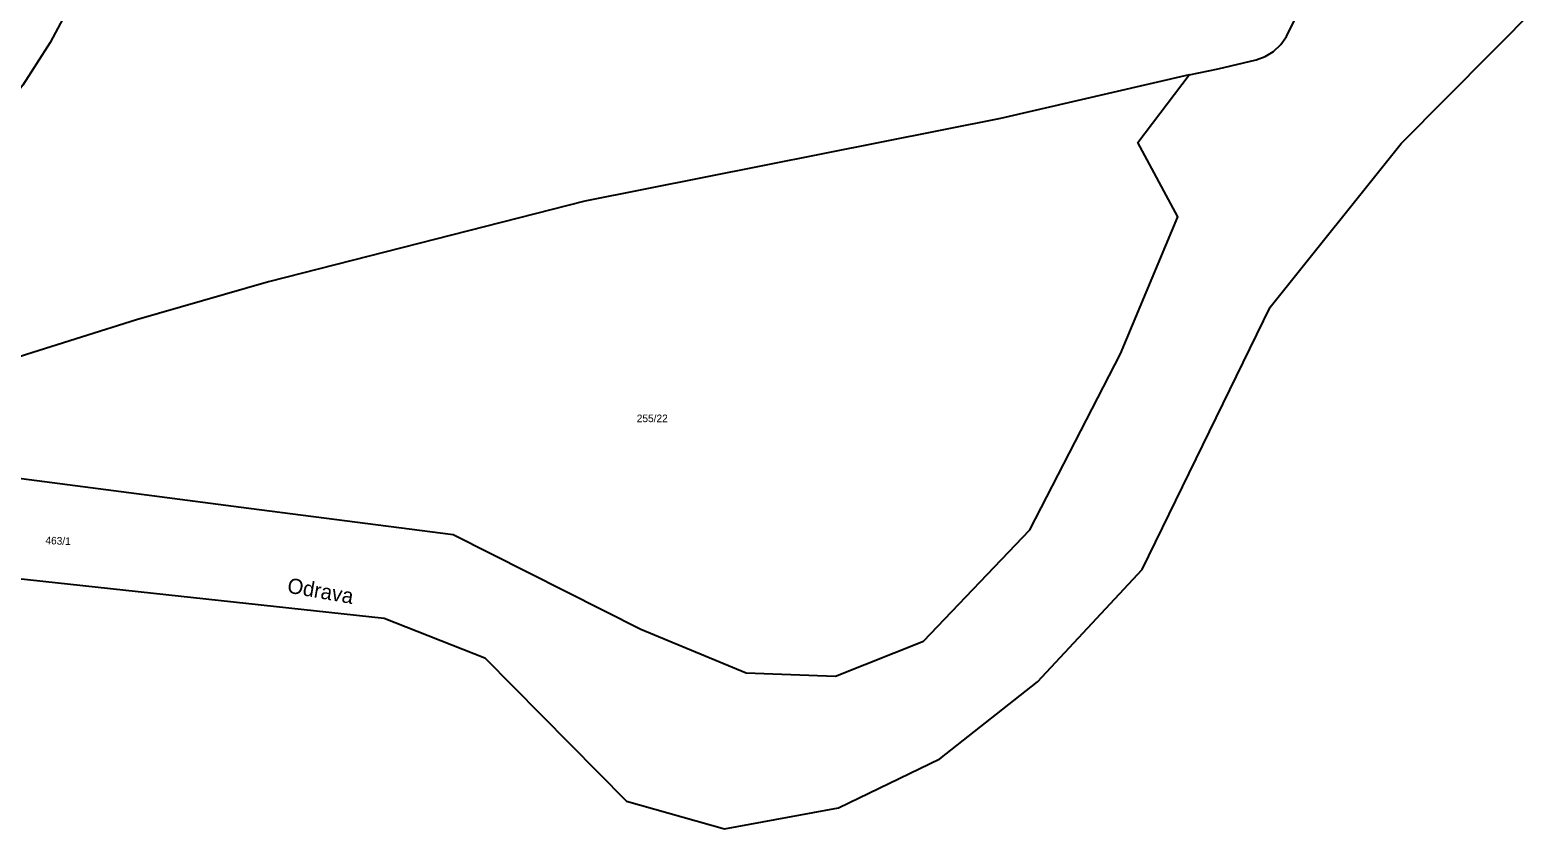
# Model space of a CAD drawing. Extents: x -882150 to -879379, y -1022570 to -1019819.
# Drawn here: x -880115.3 to -879777.5, y -1020976 to -1020796.9 of the extents above; entities that cross this region are included whole.
import ezdxf

# ---------------------------------------------------------------- set-up
doc = ezdxf.new("R2010")
doc.units = 0
for name, color, linetype in [('Hranice parcel', 7, 'Continuous'), ('Parcelní čísla', 7, 'Continuous'), ('Pop  PČ popisy', 7, 'Continuous')]:
    doc.layers.add(name, color=color, linetype=linetype)

msp = doc.modelspace()

# ---------------------------------------------------------------- linework, layer by layer
at = {"layer": 'Hranice parcel'}
msp.add_line((-880013.41, -1020937.59), (-879981.7, -1020969.74), dxfattribs=at)
for points in [[(-879855.67, -1020806.93), (-879849.12, -1020805.59), (-879840.65, -1020803.59), (-879838.63, -1020802.86), (-879836.73, -1020801.7), (-879835.11, -1020800.17), (-879833.86, -1020798.37), (-879828.56, -1020787.58), (-879810.46, -1020751.56), (-879811.09, -1020749.56), (-879813.66, -1020745.92), (-879816.39, -1020744.12), (-879819.42, -1020743.08), (-879822.57, -1020742.71), (-879825.01, -1020742.84)], [(-880104.98, -1020788.72), (-880110.84, -1020799.71), (-880116.96, -1020809.22), (-880122.17, -1020815.79)], [(-879981.7, -1020969.74), (-879959.72, -1020975.95), (-879934.19, -1020971.25), (-879911.49, -1020960.29), (-879889.63, -1020942.98), (-879866.16, -1020917.83), (-879837.52, -1020859.01), (-879808.19, -1020822.32), (-879777.54, -1020791.45)], [(-879855.67, -1020806.93), (-879897.91, -1020816.71), (-879991.04, -1020835.27), (-880061.88, -1020853.33), (-880091.47, -1020861.88), (-880116.15, -1020869.62), (-880138.18, -1020877.13), (-880170.25, -1020889.4), (-880175.6, -1020891.87), (-880180.75, -1020895.93), (-880182.85, -1020897), (-880185.19, -1020898.34), (-880186.1, -1020899.24), (-880186.44, -1020900.39), (-880186.27, -1020901.44), (-880183.95, -1020906.85), (-880183.54, -1020908.65), (-880183.84, -1020910.43), (-880184.81, -1020911.94), (-880186.2, -1020912.94), (-880194.71, -1020916.87), (-880183.87, -1020928.56), (-880181.15, -1020928.81), (-880176.17, -1020927.49)], [(-880176.17, -1020927.49), (-880173.52, -1020920.87), (-880157.73, -1020903.11), (-880135.62, -1020895), (-880066.31, -1020904.04), (-880020.56, -1020909.99), (-879978.51, -1020931.21), (-879954.91, -1020940.95), (-879934.91, -1020941.76), (-879915.17, -1020933.91), (-879891.35, -1020908.94), (-879871.04, -1020869.47), (-879858.22, -1020838.74), (-879867.14, -1020822.1), (-879855.67, -1020806.93)], [(-880124.94, -1020919.09), (-880036, -1020928.73), (-880013.41, -1020937.59)]]:
    msp.add_lwpolyline(points, dxfattribs=at)

# ---------------------------------------------------------------- texts
at = {"layer": 'Parcelní čísla'}
msp.add_text('255/22', height=1.7, dxfattribs=at).set_placement((-879979.41, -1020884.79))
msp.add_text('463/1', height=1.7, rotation=358, dxfattribs=at).set_placement((-880111.909, -1020912.129))
at = {"layer": 'Pop  PČ popisy'}
msp.add_text('Odrava', height=3.4, rotation=350, dxfattribs=at).set_placement((-880057.875, -1020922.974))

doc.saveas('drawing.dxf')
